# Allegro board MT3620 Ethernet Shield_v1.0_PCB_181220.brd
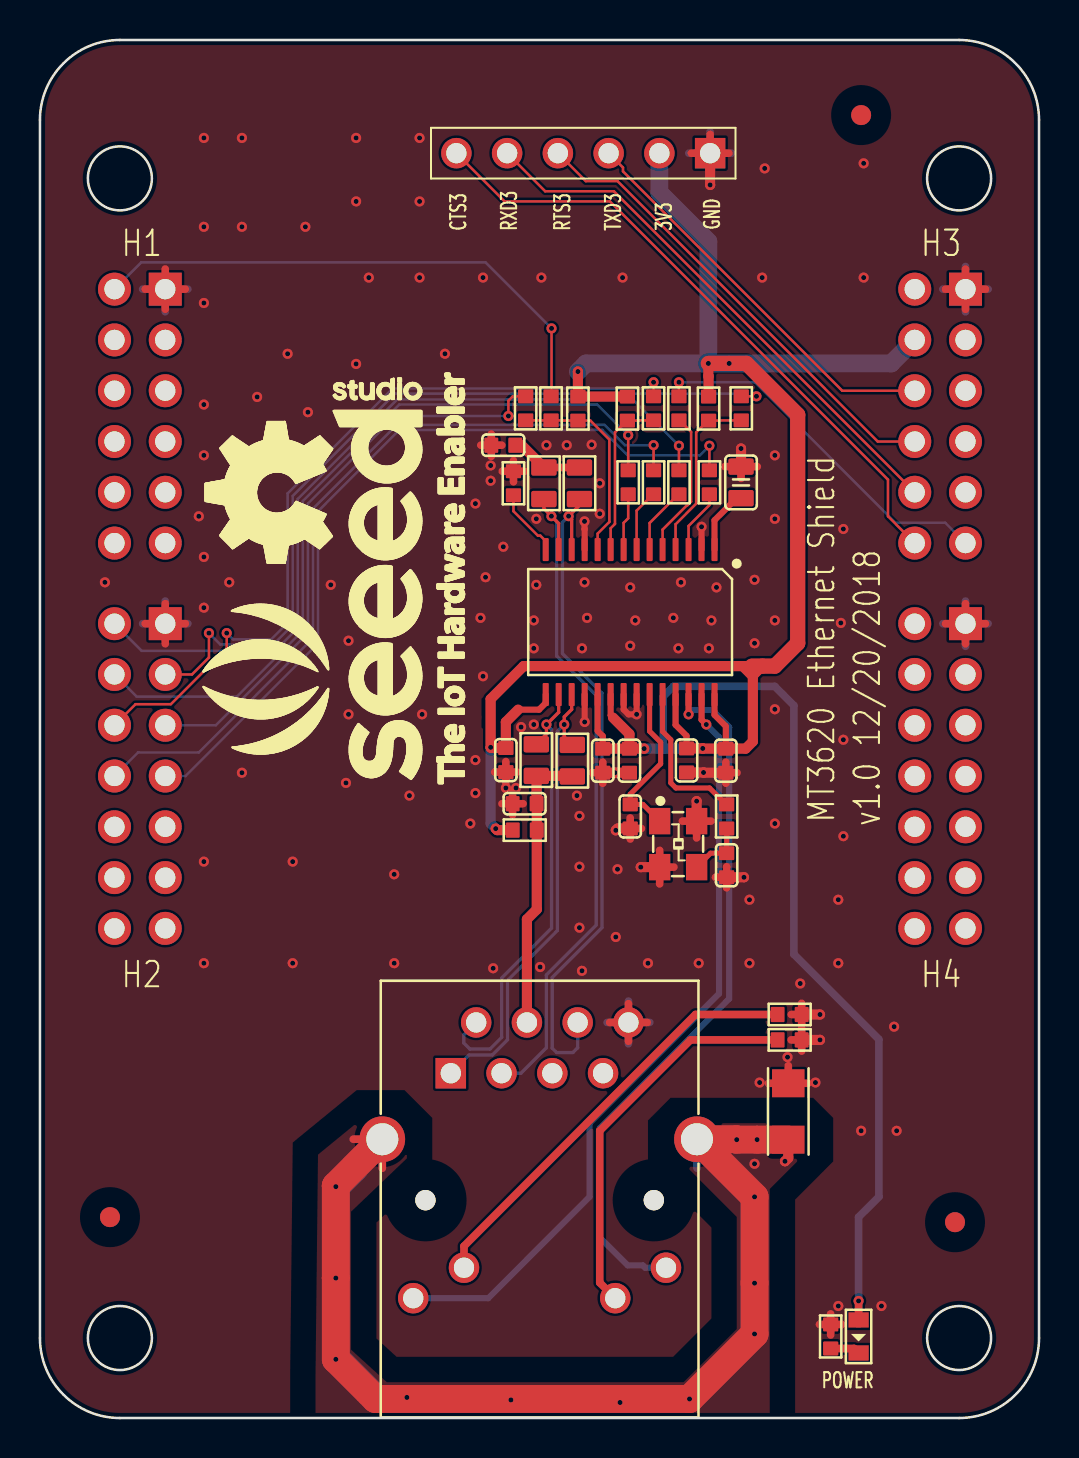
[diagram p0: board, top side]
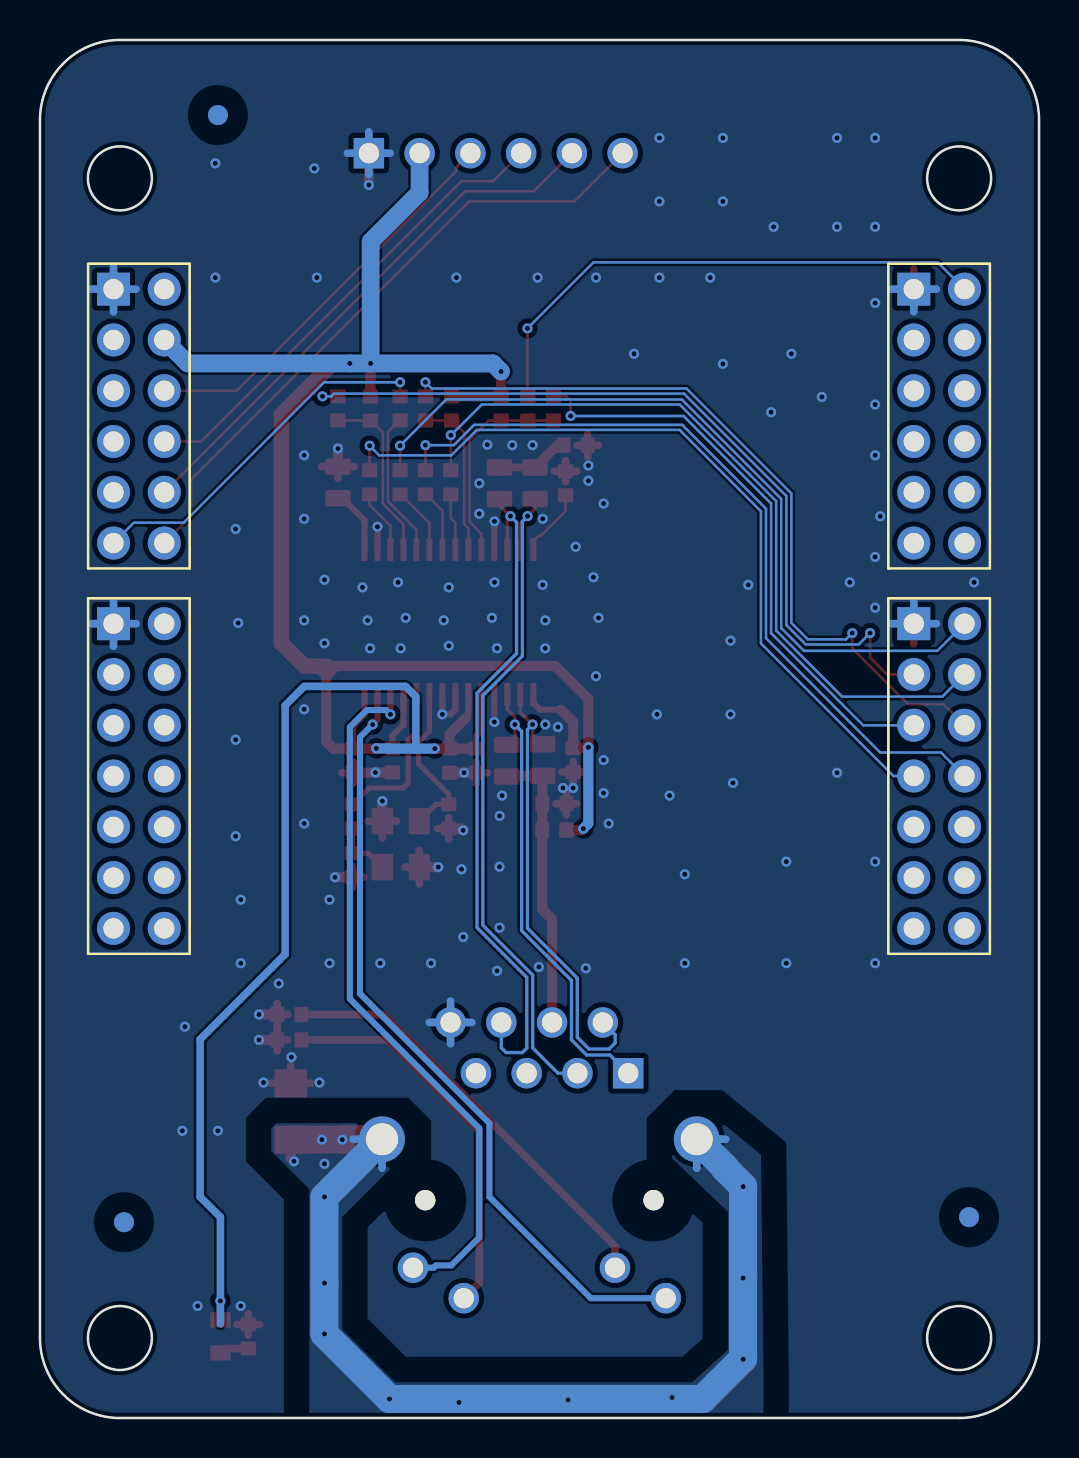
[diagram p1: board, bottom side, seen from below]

Outline 50 x 68.92 mm; copper layers: TOP, BOTTOM. Coordinates in mm from the lower left corner of the outline.
Outline path: circle c4,62 r1.6 ; circle c4,4 r1.6 ; circle c46,62 r1.6 ; circle c46,4 r1.6 ; 0,64.92 0,4 ; 0,64.92 0,4 ; 0,64.92 arc(1.17,67.75) 4,68.92 ; 0,64.92 arc(1.17,67.75) 4,68.92 ; 0,4 arc(1.17,1.17) 4,0 ; 0,4 arc(1.17,1.17) 4,0 ; 4,68.92 46,68.92 ; 4,68.92 46,68.92 ; 46,68.92 arc(48.83,67.75) 50,64.92 ; 46,68.92 arc(48.83,67.75) 50,64.92 ; 4,0 46,0 ; 4,0 46,0 ; 46,0 arc(48.83,1.17) 50,4 ; 46,0 arc(48.83,1.17) 50,4 ; 50,64.92 50,4 ; 50,64.92 50,4

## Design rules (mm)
constraint set DEFAULT: min track width 0.127
net group TPIN: nets TPIN+ TPIN-
net group TPOUT: nets TPOUT+ TPOUT-

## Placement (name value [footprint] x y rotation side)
C1  100nF  [C0603]  32.36 32.89 90 top
C2  18pF  [C0603]  29.54 30.09 90 top
C3  18pF  [C0603]  34.37 27.65 90 top
C4  100nF  [C0603]  24.25 30.72 180 top
C5  100nF  [C0603]  23.19 48.66 180 top
C6  100nF  [C0603]  34.33 32.88 270 top
C7  100nF  [C0603]  29.5 32.88 270 top
C8  100nF  [C0603]  28.17 32.88 270 top
C9  100nF  [C0603]  23.32 32.91 270 top
C10  10uF  [C0805]  35.09 46.79 90 top
FB1  120R  [L0603]  24.26 29.4 180 top
H1  Header 2x6 2.54  [HEADER2X6P_2D54_1_DIP]  5 50.11 180 bottom
H2  Header 2x7 2.54  [HEADER2X7P_2D54_1_DIP]  5 32.11 180 bottom
H3  Header 2x6 2.54  [HEADER2X6P_2D54_1_DIP]  45.05 50.11 180 bottom
H4  Header 2x7 2.54  [HEADER2X7P_2D54_1_DIP]  45.05 32.11 180 bottom
J1  HY911105T  [RJ45-7499010211A]  20.56 17.25 0 top
J2  Header 1x6 2.54mm  [HEADER6P_2D54_DIP]  33.54 63.26 270 top
LED1  Red  [LED0603]  40.97 4.08 270 top
NOREF  -  []  4 0 90 top
NOREF#2  U*  [unnamed#2]  41.1 65.17 0 top
NOREF#3  -  []  0 64.92 0 top
NOREF#4  U*  [unnamed#2]  45.8 9.79 0 top
NOREF#5  U*  [unnamed#2]  3.5 10.05 0 top
NOREF#6  U*  [unnamed#2]  45.8 9.79 180 bottom
NOREF#7  U*  [unnamed#2]  3.5 10.05 180 bottom
NOREF#8  U*  [unnamed#2]  41.1 65.17 180 bottom
R1  49.9R  [R0805]  26.64 32.88 270 top
R2  49.9R  [R0805]  25.22 46.75 90 top
R3  49.9R  [R0805]  24.84 32.91 90 top
R4  49.9R  [R0805]  27 46.75 270 top
R5  0R  [R0603]  34.37 30.09 90 top
R6  100K  [R0603]  26.92 50.49 270 top
R7  100K  [R0603]  33.46 50.49 270 top
R8  100K  [R0603]  29.4 50.49 270 top
R9  0R  [R0603]  25.58 50.5 90 top
R10  0R  [R0603]  24.31 50.5 90 top
R11  0R  [R0603]  35.1 50.5 90 top
R12  0R  [R0603]  30.71 50.5 90 top
R13  2.32K  [R0603]  23.7 46.75 90 top
R14  0R  [R0603]  29.44 46.8 90 top
R15  0R  [R0603]  30.71 46.8 90 top
R16  0R  [R0603]  31.98 46.8 90 top
R17  470R  [R0603]  37.52 20.18 0 top
R18  470R  [R0603]  37.52 18.91 0 top
R19  0R  [R0603]  33.5 46.8 90 top
R20  470R  [R0603]  39.57 4.08 90 top
R26  0R  [R1206]  37.45 15.33 90 top
R27  0R  [R0603]  31.98 50.5 90 top
U1  ENC28J60/SS  [SSOP28_0R65_10R2X5R3MM]  29.54 39.81 270 top
X1  25MHz 18pF  [X4-SMD-3_2X2_5X1_0MM]  31.94 28.7 270 top

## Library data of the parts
C1-C10 = CC
FB1 = FB_L0603_120R
H1 H3 = Header 2x6
H2 H4 = Header 2x7
J1 = RJ45_HanRun_HY911105T
J2 = Header 1x6
LED1 = Single LED
R1-R20 R26 R27 = R
U1 = ENC28J60
X1 = XTAL_4P

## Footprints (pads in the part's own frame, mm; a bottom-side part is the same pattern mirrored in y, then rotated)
C0603
  rrect 0.696x0.762 smd: 1(-0.602,0) 2(0.602,0)
C0805
  rrect 0.819x1.27 smd: 1(-0.79,0) 2(0.79,0)
HEADER2X6P_2D54_1_DIP
  rect 1.651x1.651 hole 1.016: 1(-1.27,6.35)
  round 1.651 hole 1.016: 2(1.27,6.35) 3(-1.27,3.81) 4(1.27,3.81) 5(-1.27,1.27) 6(1.27,1.27) 7(-1.27,-1.27) 8(1.27,-1.27) 9(-1.27,-3.81) 10(1.27,-3.81) 11(-1.27,-6.35) 12(1.27,-6.35)
HEADER2X7P_2D54_1_DIP
  rect 1.651x1.651 hole 1.016: 1(-1.27,7.62)
  round 1.651 hole 1.016: 2(1.27,7.62) 3(-1.27,5.08) 4(1.27,5.08) 5(-1.27,2.54) 6(1.27,2.54) 7(-1.27,0) 8(1.27,0) 9(-1.27,-2.54) 10(1.27,-2.54) 11(-1.27,-5.08) 12(1.27,-5.08) 13(-1.27,-7.62) 14(1.27,-7.62)
HEADER6P_2D54_DIP
  rect 1.524x1.524 hole 1.016: 1(0,0)
  round 1.524 hole 1.016: 2(0,-2.54) 3(0,-5.08) 4(0,-7.62) 5(0,-10.16) 6(0,-12.7)
L0603
  rrect 0.696x0.762 smd: 1(-0.602,0) 2(0.602,0)
LED0603
  rect 0.762x1.016 smd: 1(-0.826,0) 2(0.826,0)
R0603
  rrect 0.696x0.762 smd: 1(-0.602,0) 2(0.602,0)
R0805
  rrect 0.819x1.27 smd: 1(-0.79,0) 2(0.79,0)
R1206
  rect 1.397x1.626 smd: 1(-1.41,0) 2(1.41,0)
RJ45-7499010211A
  round 1.016 hole 3.251 unplated: (-1.27,-6.35) (10.16,-6.35)
  rect 1.524x1.524 hole 1.016: 1(0,0)
  round 1.524 hole 1.016: 2(1.27,2.54) 3(2.54,0) 4(3.81,2.54) 5(5.08,0) 6(6.35,2.54) 7(7.62,0) 8(8.89,2.54) 9(-1.88,-11.252) 10(0.66,-9.728) 11(8.23,-11.252) 12(10.77,-9.728)
  round 2.286 hole 1.6: 13(-3.429,-3.302) 14(12.319,-3.302)
SSOP28_0R65_10R2X5R3MM
  rrect 1.15x0.3 smd: 1(-3.625,4.225) 2(-3.625,3.575) 3(-3.625,2.925) 4(-3.625,2.275) 5(-3.625,1.625) 6(-3.625,0.975) 7(-3.625,0.325) 8(-3.625,-0.325) 9(-3.625,-0.975) 10(-3.625,-1.625) 11(-3.625,-2.275) 12(-3.625,-2.925) 13(-3.625,-3.575) 14(-3.625,-4.225) 15(3.625,-4.225) 16(3.625,-3.575) 17(3.625,-2.925) 18(3.625,-2.275) 19(3.625,-1.625) 20(3.625,-0.975) 21(3.625,-0.325) 22(3.625,0.325) 23(3.625,0.975) 24(3.625,1.625) 25(3.625,2.275) 26(3.625,2.925) 27(3.625,3.575) 28(3.625,4.225)
unnamed#2
  round 1 smd: 1(0,0)
X4-SMD-3_2X2_5X1_0MM
  rect 1.321x1.067 smd: 1(-1.15,-0.925) 2(1.15,-0.925) 3(1.15,0.925) 4(-1.15,0.925)

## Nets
GND: C1.1 C2.1 C3.1 C4.2 C5.2 C6.2 C7.2 C8.2 C9.2 C10.2 H1.1 H2.1 H3.1 H4.1 J1.8 J2.1 R13.2 R17.2 R18.2 R20.2 R26.2 U1.2 U1.11 U1.18(VSSTX) U1.21 U1.22 X1.2 X1.4
GND_EARTH: J1.13 J1.14 R26.1
VDD_3V3: C1.2 C6.1 C7.1 C8.1 C9.1 FB1.2 H3.4 J2.2 LED1.1 R6.1 R7.1 R8.1 U1.15 U1.19 U1.20 U1.25 U1.28
CLKOUT: R19.1 U1.3
CS: R8.2 R12.1 U1.9
GPIO5_INT: H2.3 R11.2
GPIO6_RST: H2.5 R10.2
GPIO7_CLKOUT: H2.7 R19.2
GPIO26_SCLK0: H2.4 R14.2
GPIO27_MOSI0: H2.8 R15.2
GPIO28_MISO0: H2.2 R16.2
GPIO29_CSA0: H2.6 R12.2
GPIO66_TXD3: H3.6 J2.3
GPIO67_RTS3: H3.8 J2.4
GPIO68_RXD3: H3.10 J2.5
GPIO69_CTS3: H3.12 J2.6
GPIO70_WOL: H3.11 R27.2
INT: R7.2 R11.1 U1.4
LED-: LED1.2(C) R20.1
LEDA: J1.9 U1.27
LEDA-: J1.10 R17.1
LEDB: J1.12 U1.26
LEDB-: J1.11(YELC) R18.1
OSC1: C2.2 U1.23 X1.1
OSC2: R5.2 U1.24
OSC2_R: C3.2 R5.1 X1.3
RBIAS: R13.1 U1.14
RESET: R6.2 R9.1 R10.1 U1.10
SCK: R14.1 U1.8
SI: R15.1 U1.7
SO: R16.1 U1.6
SYS_RST_B: H1.2 R9.2
TPIN+: J1.3 R2.1 U1.13
TPIN-: J1.6 R4.2 U1.12
TPOUT+: J1.1 R1.1 U1.17
TPOUT-: J1.2 R3.2 U1.16
TPOUT_CT: C4.1 FB1.1 J1.4 R1.2 R3.1
VCAP: C10.1 U1.1
WOL: R27.1 U1.5
N25389849: C5.1 R2.2 R4.1

Pads without a net: H1 3 4 5 6 7 8 9 10 11 12; H2 9 10 11 12 13 14; H3 2 3 5 7 9; H4 2 3 4 5 6 7 8 9 10 11 12 13 14; J1 5 7; NOREF#2 1; NOREF#4 1; NOREF#5 1; NOREF#6 1; NOREF#7 1; NOREF#8 1

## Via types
v1: diameter 0.508, hole 0.254, TOP to BOTTOM, 167 vias

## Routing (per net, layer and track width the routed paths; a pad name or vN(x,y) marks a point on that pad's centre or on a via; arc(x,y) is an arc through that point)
GND: length 95.5
  TOP w0.127: 23.32,31.78 v1(23.32,31.51) ; 23.65,31.34 v1(23.82,31.51)
  TOP w0.305: v1(27.25,44.85) 27.25,44.46 27.26,44.46 U1.11 ; U1.2 v1(33.11,44.58) ; U1.22 v1(29.86,35.19) 29.45,35.19 29.21,35.44 U1.21 ; U1.18 v1(27.26,34.81)
  TOP w0.381: 37.6,20.18 R17.2 ; R17.2 38.12,20.74 ; R17.2 38.12,19.62 ; J1.8 30.39,19.79 ; J1.8 29.45,20.73 ; J1.8 28.51,19.79 ; J1.8 29.45,18.84 ; C10.2 35.9,47.58 ; C10.2 34.27,47.58 ; C10.2 35.09,47 ; 39.01,4.68 R20.2 ; R20.2 40.13,4.68 ; R20.2 39.57,4.15 ; R20.2 39.57,5.21 ; 46.32,55.46 H3.1 ; H3.1 47.32,56.46 ; H3.1 45.32,56.46 ; H3.1 46.32,57.46 ; C4.2 23.65,31.28 ; C4.2 24.18,30.72 ; C4.2 23.13,30.72 ; C4.2 23.65,30.16 ; C6.2 34.33,32.8 ; C6.2 34.89,32.28 ; C6.2 34.33,31.75 ; 32.15,29.85 X1.4 ; X1.4 33.58,29.85 ; X1.4 32.86,29.01 ; 37.6,18.91 R18.2 ; R18.2 38.12,18.35 ; R18.2 38.12,19.47 ; 46.32,38.73 H4.1 ; H4.1 47.32,39.73 ; H4.1 45.32,39.73 ; H4.1 46.32,40.73 ; 23.32,31.78 C9.2 ; C9.2 23.88,32.31 ; C9.2 23.32,32.83 ; C9.2 22.76,32.31 ; 6.27,38.73 H2.1 ; H2.1 5.27,39.73 ; H2.1 6.27,40.73 ; H2.1 7.27,39.73 ; C2.1 30.1,29.49 ; C2.1 29.54,28.96 ; C2.1 29.54,30.01 ; 22.59,48.1 C5.2 ; C5.2 22.59,49.21 ; C5.2 22.06,48.66 ; C5.2 23.11,48.66 ; R26.2 37.45,17.62 ; R26.2 38.44,16.74 ; R26.2 36.46,16.74 ; 31.01,26.71 X1.2 ; X1.2 31.73,27.55 ; X1.2 31.01,28.39 ; R13.2 24.26,47.35 ; R13.2 23.7,46.83 ; R13.2 23.14,47.35 ; R13.2 23.7,47.88 ; 32.6,63.26 J2.1 ; J2.1 34.48,63.26 ; J2.1 33.54,64.2 ; 27.61,32.28 C8.2 ; C8.2 28.17,32.8 ; C8.2 28.17,31.75 ; H1.1 7.27,56.46 ; H1.1 6.27,55.46 ; H1.1 6.27,57.46 ; H1.1 5.27,56.46 ; 33.81,27.04 C3.1 ; C3.1 34.37,26.52 ; C3.1 34.37,27.57
  TOP w0.508: C6.2 33.22,32.28 v1(33.21,32.29) C1.1 ; C10.2 v1(35.09,48.49) ; C3.1 v1(35.23,27.04) ; J2.1 v1(33.54,61.67) ; v1(28.82,29.39) 28.91,29.49 C2.1 ; X1.4 v1(32.86,30.85) ; R17.2 v1(39.04,20.18) ; R18.2 v1(39.04,18.91) ; C8.2 v1(28.78,32.28) C7.2 ; X1.2 v1(30.07,27.55)
  BOTTOM w0.381: 5.14,56.46 H1.1 ; H1.1 7.4,56.46 ; H1.1 6.27,55.33 ; 45.19,56.46 H3.1 ; H3.1 47.45,56.46 ; H3.1 46.32,57.59 ; H3.1 46.32,55.33 ; 45.19,39.73 H4.1 ; H4.1 46.32,40.86 ; H4.1 46.32,38.6 ; H4.1 47.45,39.73 ; 28.38,19.79 J1.8 ; J1.8 29.45,18.72 ; J1.8 30.52,19.79 ; J1.8 29.45,20.85 ; 33.54,62.19 J2.1 ; J2.1 34.61,63.26 ; J2.1 32.47,63.26 ; J2.1 33.54,64.33 ; H2.1 7.4,39.73 ; H2.1 6.27,40.86 ; H2.1 5.14,39.73
  vias: v1(3.25,41.8) v1(7.95,45.1) v1(8.2,64.02) v1(8.2,59.58) v1(8.2,55.77) v1(8.2,50.69) v1(8.2,48.15) v1(8.2,43.07) v1(8.2,40.53) v1(8.2,27.83) v1(8.2,22.75) v1(9.47,41.8) v1(10.11,64.02) v1(10.11,59.58) v1(10.11,32.27) v1(10.87,51.07) v1(12.39,53.23) v1(12.65,27.83) v1(12.65,22.75) v1(13.28,59.58) v1(13.41,50.31) v1(14.55,41.67) v1(15.32,31.76) v1(15.44,38.88) v1(15.44,35.19) v1(15.82,64.02) v1(15.82,60.85) v1(15.82,52.72) v1(16.46,57.04) v1(17.73,27.19) v1(17.73,22.75) v1(18.49,31.13) v1(19,64.02) v1(19,60.85) v1(19,57.04) v1(19.13,35.19) v1(20.27,53.23) v1(21.54,29.73) v1(21.79,45.73) v1(21.79,32.91) v1(21.79,31.26) v1(22.05,40.02) v1(22.17,57.04) v1(22.17,37.1) v1(22.3,42.05) v1(22.55,47.64) v1(22.55,46.88) v1(22.68,22.49) v1(23.19,43.58) v1(24.08,34.56) v1(24.71,39.89) v1(24.71,38.5) v1(24.71,34.69) v1(24.84,44.97) v1(24.84,41.67) v1(25.03,22.56) v1(25.09,57.04) v1(25.35,48.66) v1(26.36,48.66) v1(26.87,31.13) v1(27,30.11) v1(27,27.57) v1(27,24.53) v1(27.13,38.5) v1(27.13,22.37) v1(27.25,41.8) v1(27.38,40.02) v1(27.61,48.68) v1(28.02,46.75) v1(28.02,45.23) v1(28.82,24.06) v1(28.9,27.45) v1(29.16,57.04) v1(29.54,41.54) v1(29.54,38.62) v1(29.79,39.89) v1(30.43,22.75) v1(31.7,40.02) v1(31.95,38.5) v1(32.08,41.8) v1(32.97,22.75) v1(33.48,38.5) v1(33.6,39.89) v1(33.86,41.54) v1(35.51,25.92) v1(35.51,22.75) v1(35.76,41.92) v1(35.76,38.75) v1(36.02,16.78) v1(36.14,57.04) v1(36.27,62.5) v1(36.78,48.15) v1(36.78,44.97) v1(36.78,39.89) v1(36.78,35.45) v1(36.78,29.73) v1(37.41,18.05) v1(38.05,21.73) v1(38.81,16.78) v1(39.95,25.92) v1(39.95,22.75) v1(39.95,5.6) v1(40.08,39.77) v1(40.21,44.46) v1(40.21,33.92) v1(40.21,29.1) v1(41.1,14.37) v1(41.22,62.75) v1(41.22,57.04) v1(42.11,5.6) v1(42.75,19.57) v1(42.87,14.37)
GND_EARTH: length 106.4
  TOP w0.381: 15.68,13.94 J1.13 17.13,12.49
  TOP w0.508: R26.1 37.45,13.01 v1(37.29,12.84)
  TOP w1.397: J1.13 14.81,11.62 v1(14.81,11.57) v1(14.81,7) v1(14.81,2.94) 16.79,0.95 v1(32.51,0.95) v1(35.76,4.21) v1(35.76,6.75) v1(35.76,11.06) J1.14 34.85,13.94 v1(34.87,13.92) v1(35.89,13.92) R26.1
  BOTTOM w0.381: 32.88,12.49 J1.14 34.33,13.94 ; 15.68,13.94 J1.13 17.13,12.49
  BOTTOM w1.397: J1.14 v1(35.76,11.06) v1(35.76,6.75) v1(35.76,4.21) v1(32.51,0.95) 16.84,0.95 14.81,2.98 v1(14.81,7) v1(14.81,11.57) 15.74,12.5 15.74,12.55 J1.13
  vias: v1(18.36,1.03) v1(23.57,0.9) v1(29.03,0.78) v1(35.76,12.71)
VDD_3V3: length 149
  TOP w0.305: U1.20 28.56,35.15 28.68,35.03 ; U1.19 27.91,34.36 28.17,34.11 C8.1 ; U1.28 33.76,35.16 34.33,34.6 C6.1 ; C1.2 32.36,34.12 31.81,34.67 U1.25 ; U1.15 25.31,35.76 24.98,35.43 23.93,35.43
  TOP w0.381: LED1.1 v1(40.97,5.86)
  TOP w0.508: 28.68,35.03 29.5,34.21 C7.1 ; 35.17,37.61 24.21,37.61 22.55,35.96 v1(22.55,33.54) 22.59,33.51 C9.1 23.32,34.81 23.93,35.43 ; 35.17,37.61 35.64,37.61 ; 35.17,37.61 35.68,37.1 ; 36.14,37.61 35.68,37.14 35.68,37.1 ; 35.68,37.1 35.68,33.84 35.32,33.48 C6.1 33.18,33.48 v1(33.17,33.49) C1.2 ; v1(22.81,29.48) 22.88,29.4 FB1.2 ; v1(33.45,52.74) 33.45,52.11 33.46,52.1 R7.1 ; v1(26.92,52.34) R6.1 R8.1 ; C7.1 v1(30.24,33.48) ; C7.1 C8.1
  TOP w0.762: v1(33.45,52.74) v1(34.49,52.74) 35.36,52.74 37.92,50.18 37.92,38.75 36.78,37.61 35.64,37.61
  BOTTOM w0.381: 31.19,33.48 31.19,36.08 31.7,36.59 36.78,36.59 37.73,35.64 37.73,23.19 41.99,18.94 41.99,11.06 40.97,10.05 v1(40.97,5.86) 40.97,4.71
  BOTTOM w0.508: v1(33.17,33.49) 32.53,33.49 32.52,33.48 v1(30.24,33.48) ; v1(22.55,33.54) 22.55,29.73 v1(22.81,29.48)
  BOTTOM w0.889: v1(26.92,52.34) 27.33,52.74 v1(33.45,52.74) ; v1(33.45,52.74) 33.45,58.84 31,61.29 J2.2 ; v1(33.45,52.74) v1(34.49,52.74) 42.6,52.74 H3.4
CLKOUT: length 3.2
  TOP w0.127: U1.3 32.46,44.62 33.5,45.66 R19.1
CS: length 8.1
  TOP w0.127: R12.1 29.98,49.9 29.97,49.89 R8.2 29.37,49.89 28.78,49.3 28.78,44.72 28.56,44.5 U1.9
GPIO5_INT: length 41.2
  TOP w0.127: H2.3 7.61,37.19 8.46,38.04 v1(8.46,39.26) ; R11.2 v1(35.86,51.1)
  BOTTOM w0.127: v1(35.86,51.1) 35.41,51.1 35.28,51.24 17.77,51.24 12.65,46.12 12.65,39.66 11.68,38.69 9.03,38.69 v1(8.46,39.26)
GPIO6_RST: length 29.1
  TOP w0.127: R10.2 23.66,51.1 23.44,50.88 v1(23.44,50.12)
  BOTTOM w0.127: H2.5 8.8,34.65 13.41,39.26 13.41,45.73 17.79,50.12 v1(23.44,50.12)
GPIO7_CLKOUT: length 40.2
  TOP w0.127: R19.2 v1(33.5,48.63)
  BOTTOM w0.127: H2.7 7.29,32.11 13.92,38.74 13.92,45.35 17.98,49.42 28.14,49.42 29.41,48.15 33.02,48.15 v1(33.5,48.63)
GPIO26_SCLK0: length 38.4
  TOP w0.127: R14.2 v1(29.44,49.16)
  BOTTOM w0.127: H2.4 4.84,36.08 9.85,36.08 13.16,39.38 13.16,45.86 17.98,50.69 27.89,50.69 29.11,49.47 29.12,49.47 v1(29.44,49.16)
GPIO27_MOSI0: length 39.7
  TOP w0.127: R15.2 v1(30.71,48.66)
  BOTTOM w0.127: v1(30.71,48.66) 29.29,48.66 28.27,49.67 17.86,49.67 13.66,45.48 13.66,39 7.95,33.29 4.91,33.29 H2.8
GPIO28_MISO0: length 40
  TOP w0.127: R16.2 v1(31.98,48.63)
  BOTTOM w0.127: H2.2 5.09,38.37 11.76,38.37 12.9,39.51 12.9,45.97 17.88,50.94 29.67,50.94 v1(31.98,48.63)
GPIO29_CSA0: length 39.3
  TOP w0.127: R12.2 v1(30.71,51.8) ; v1(9.35,39.26) 9.35,38.5 6.55,35.7 4.78,35.7 H2.6
  BOTTOM w0.127: v1(30.71,51.8) 30.39,51.49 17.64,51.49 12.39,46.24 12.39,39.77 11.57,38.94 9.66,38.94 v1(9.35,39.26)
GPIO66_TXD3: length 20.4
  TOP w0.127: H3.6 40.15,51.38 29.18,62.35 29.18,62.54 J2.3
GPIO67_RTS3: length 23.8
  TOP w0.127: H3.8 41.93,48.84 28.9,61.86 27.32,61.86 J2.4
GPIO68_RXD3: length 27.4
  TOP w0.127: H3.10 28.72,61.36 25.28,61.36 J2.5
GPIO69_CTS3: length 32.1
  TOP w0.127: J2.6 23.25,60.85 28.52,60.85 42.44,46.93 42.44,45.1 H3.12
GPIO70_WOL: length 18.4
  TOP w0.127: R27.2 v1(31.98,51.8)
  BOTTOM w0.127: H3.11 45.3,44.78 42.81,44.78 35.78,51.8 v1(31.98,51.8)
INT: length 8.8
  TOP w0.127: U1.4 31.81,44.7 32.84,45.73 32.84,49.3 33.43,49.89 R7.2 34.03,49.89 34.04,49.9 R11.1
LED-: length 1.5
  TOP w0.381: R20.1 40.75,3.48 LED1.2
LEDA: length 39.1
  TOP w0.305: v1(33.35,34.69) 33.11,34.92 U1.27
  BOTTOM w0.305: J1.9 22.44,5.99 27.51,11.06 27.51,14.75 33.98,21.22 33.98,34.05 v1(33.35,34.69)
LEDA-: length 21.6
  TOP w0.381: R17.1 32.81,20.18 21.22,8.6 J1.10
LEDB: length 35.6
  TOP w0.305: U1.26 v1(32.46,35.19)
  BOTTOM w0.305: v1(32.46,35.19) 32.68,35.41 33.64,35.41 34.49,34.56 34.49,20.97 28.02,14.49 28.02,9.03 29.41,7.63 30.17,7.63 30.29,7.52 J1.12
LEDB-: length 19.5
  TOP w0.381: R18.1 32.56,18.91 28.02,14.37 28.02,6.77 J1.11
OSC1: length 8.2
  TOP w0.254: U1.23 30.51,34.35 31.06,33.8 31.06,32.72 29.54,31.2 C2.2 30.18,30.69 X1.1
OSC2: length 7.8
  TOP w0.254: R5.2 34.33,30.69 33.51,31.51 31.83,31.51 31.57,31.76 31.57,33.92 31.16,34.33 U1.24
OSC2_R: length 3
  TOP w0.254: X1.3 33.56,28.25 C3.2 R5.1
RBIAS: length 3.5
  TOP w0.127: U1.14 25.31,43.86 25.04,44.13 24.92,44.13 23.7,45.35 R13.1
RESET: length 10.3
  TOP w0.127: U1.10 27.91,44.23 28.5,44.82 28.5,48.94 27.55,49.89 R6.2 26.16,49.89 26.15,49.9 R9.1 R10.1
SCK: length 2.9
  TOP w0.127: U1.8 29.21,44.77 29.44,45 R14.1
SI: length 3.1
  TOP w0.127: R15.1 30.68,46.2 29.86,45.38 U1.7
SO: length 3.4
  TOP w0.127: R16.1 31.95,46.2 30.51,44.76 U1.6
SYS_RST_B: length 27.2
  TOP w0.127: v1(25.6,54.5) 25.6,51.12 R9.2
  BOTTOM w0.127: H1.2 5.07,57.8 22.3,57.8 v1(25.6,54.5)
TPIN+: length 34.1
  TOP w0.165: R2.1 25.22,45.48 v1(25.6,45.11) 25.96,44.74 U1.13
  BOTTOM w0.165: J1.3 24.07,17.25 25.34,18.51 25.34,22.16 27.84,24.65 27.84,36.13 25.86,38.11 25.86,44.85 v1(25.6,45.11)
TPIN-: length 34.1
  TOP w0.165: R4.2 27,45.65 v1(26.46,45.11) 26.61,44.95 U1.12
  BOTTOM w0.165: v1(26.46,45.11) 26.15,44.8 26.15,38.24 28.13,36.25 28.13,24.53 25.63,22.04 25.63,18.5 25.86,18.28 26.67,18.28 26.91,18.52 J1.6
TPOUT+: length 23.3
  TOP w0.165: U1.17 26.61,35.44 26.24,35.07 v1(26.24,34.69) 26.24,34.07 R1.1
  BOTTOM w0.165: v1(26.24,34.69) 25.89,34.34 25.89,24.38 23.4,21.88 23.4,18.92 22.64,18.16 21.47,18.16 J1.1
TPOUT-: length 23.3
  TOP w0.165: U1.16 25.96,35.3 v1(25.35,34.69) 25.35,34.21 R3.2
  BOTTOM w0.165: v1(25.35,34.69) 25.6,34.43 25.6,24.5 23.11,22.01 23.11,19.04 22.52,18.45 21.51,18.45 21.21,18.76 21.21,19.16 J1.2
TPOUT_CT: length 14.4
  TOP w0.508: R1.2 26.61,32.12 R3.1 24.86,32.1 C4.1 24.86,30.72 FB1.1 24.86,25.44 24.37,24.95 J1.4
VCAP: length 3.2
  TOP w0.305: C10.1 34.86,46 33.76,44.9 U1.1
WOL: length 7.3
  TOP w0.127: U1.5 31.16,44.43 32.38,45.66 32.41,45.66 32.59,45.84 32.59,49.32 32.01,49.9 R27.1
N25389849: length 3.7
  TOP w0.381: R2.2 R4.1
  TOP w0.508: R2.2 24.11,48.66 C5.1

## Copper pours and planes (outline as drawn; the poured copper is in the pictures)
GND on TOP: 0.26,64.92 1.35,67.57 4,68.67 46,68.67 48.65,67.57 49.74,64.92 49.74,4 48.65,1.35 46,0.26 37.79,0.26 37.79,10.93 39.7,12.83 39.7,15.01 38.69,16.02 31.56,16.02 30.43,14.88 30.43,12.71 33.6,9.53 33.6,4.98 31.69,3.06 17.85,3.06 16.84,3.98 16.84,9.78 19.63,12.44 19.63,15.01 18.25,16.4 15.85,16.4 12.65,13.78 12.52,2.18 12.52,0.26 4,0.26 1.35,1.35 0.26,4 ; 9 cut-outs
GND on BOTTOM: 4,0.26 1.35,1.35 0.26,4 0.26,64.92 1.35,67.57 4,68.67 46,68.67 48.65,67.57 49.74,64.92 49.74,4 48.65,1.35 46,0.26 37.79,0.26 37.79,10.93 39.7,12.83 39.7,15.01 38.69,16.02 31.56,16.02 30.43,14.88 30.43,12.71 33.6,9.53 33.6,4.98 31.69,3.06 17.85,3.06 16.84,3.98 16.84,9.78 19.63,12.44 19.63,15.01 18.25,16.4 15.85,16.4 12.65,13.78 12.52,2.18 12.52,0.26 ; 9 cut-outs
GND_EARTH on TOP, BOTTOM: 13.79,0.26 13.79,2.17 13.92,13.17 16.3,15.13 17.72,15.13 18.36,14.48 18.36,12.99 15.57,10.32 15.57,3.42 17.36,1.79 32.22,1.79 34.87,4.45 34.87,10.06 31.7,13.23 31.7,14.36 32.09,14.75 38.17,14.75 38.43,14.48 38.43,13.36 36.52,11.45 36.52,0.26

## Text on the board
Ref Des/Silkscreen Top: POWER | CTS3 | RXD3 | RTS3 | TXD3 | 3V3 | GND | (OZ) | H1 | H2 | H3 | H4 | MT3620 Ethernet Shield | v1.0 12/20/2018 | LAYER 2 - SECONDARY SIDE - SIGNAL | LAYER 1 - PRIMARY SIDE - SIGNAL | LAYER# | COPPER WEIGHT | HALF+PLATING | IMPEDANCE CONTROL | +/- 10% | 50ohm SINGLE ENDED | TRACE WIDTH | TRACE WIDTH / SPACE | 90ohm DIFFERENTIAL | 100ohm DIFFERENTIAL | 1 | 6.5/5 | LAYER STACK-UP - ALL DIMENSIONS IN INCHES
User.26: FIGURE | FINISHED_SIZE | 10.0 | 40.0 | 63.0 | 128.0 | DRILL CHART: TOP to BOTTOM | ALL UNITS ARE IN MILS | TOLERANCE_DRILL | +0.0/-0.0 | +3.0/-3.0 | +5.0/-5.0 | PLATED | NON-PLATED | QTY | 167 | 52 | 18 | 2
